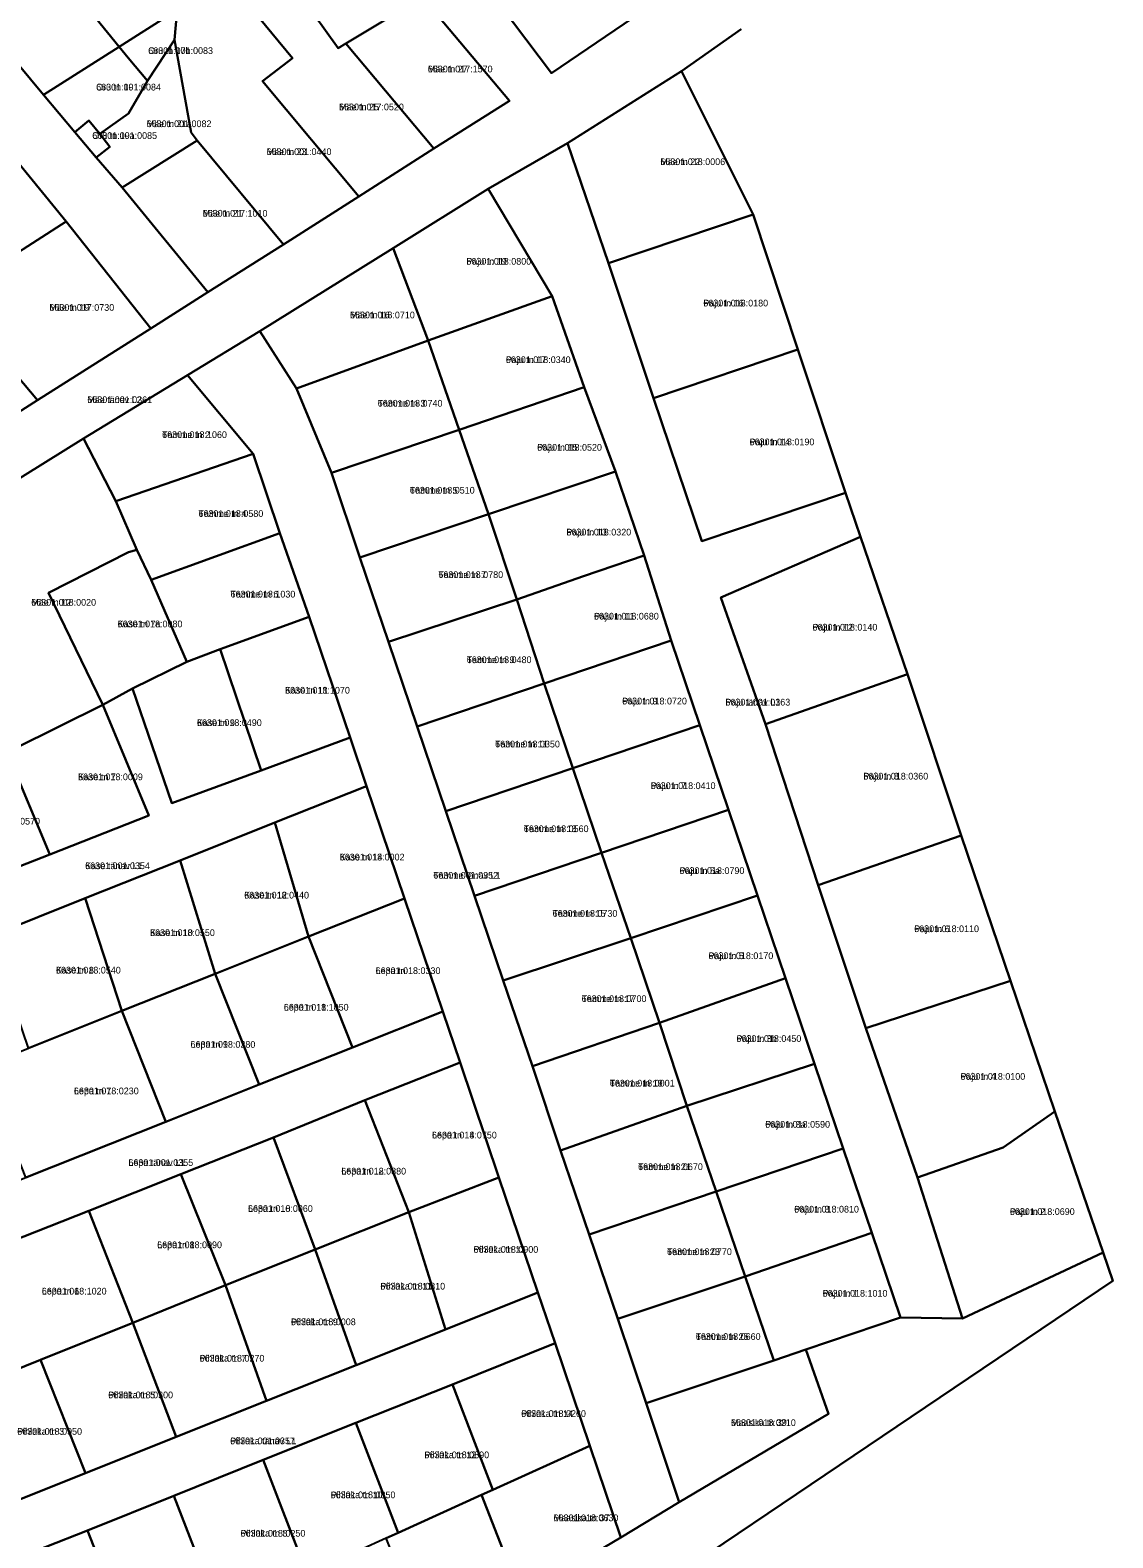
# Model space of a CAD drawing. Extents: x 632278 to 636344, y 6578401 to 6583362.
# Drawn here: x 634681.3 to 634923.7, y 6579573.7 to 6579911.1 of the extents above; entities that cross this region are included whole.
import ezdxf

# ---------------------------------------------------------------- set-up
doc = ezdxf.new("R2010")
doc.units = 0
for name, color, linetype in [('L_AADRESS', 7, 'Continuous'), ('PIIR', 7, 'Continuous'), ('TUNNUS', 7, 'Continuous')]:
    doc.layers.add(name, color=color, linetype=linetype)

msp = doc.modelspace()

# ---------------------------------------------------------------- linework, layer by layer
at = {"layer": 'PIIR'}
for points in [[(634732.89, 6580024.54), (634829.01, 6580019.04), (634843.75, 6579980.63), (634826.43, 6579969), (634849.45, 6579936.6), (634838.42, 6579929.05), (634798.01, 6579901.48), (634781.03, 6579924.08), (634761.47, 6579947.6), (634728.84, 6579986.89), (634732.38, 6580010.94)], [(634682.27, 6579930.7), (634698.8, 6579941.36), (634713.35, 6579923.81), (634714.62, 6579922.27), (634714.27, 6579915.65), (634712.52, 6579914.54), (634701.22, 6579907.36)], [(634769.15, 6579918.49), (634752.02, 6579908.13), (634750.26, 6579907.07), (634733.98, 6579929.82), (634752.56, 6579941.83), (634770.4, 6579919.25)], [(634682.27, 6579930.7), (634701.22, 6579907.36), (634684.34, 6579896.64), (634664.99, 6579919.9)], [(634740.03, 6579904.85), (634730.81, 6579916.04), (634729.25, 6579926.79), (634733.98, 6579929.82), (634750.26, 6579907.07), (634752.02, 6579908.13), (634771.69, 6579884.62), (634754.9, 6579873.86), (634733.36, 6579899.72)], [(634738.01, 6579863.17), (634718.71, 6579886.44), (634717.38, 6579888.19), (634713.63, 6579908.98), (634714.27, 6579915.65), (634714.62, 6579922.27), (634724.25, 6579924.06), (634730.81, 6579916.04), (634740.03, 6579904.85), (634733.36, 6579899.72), (634754.9, 6579873.86)], [(634769.15, 6579918.49), (634788.63, 6579895.28), (634771.69, 6579884.62), (634752.02, 6579908.13)], [(634703.24, 6579904.94), (634701.22, 6579907.36), (634712.52, 6579914.54), (634714.27, 6579915.65), (634713.63, 6579908.98), (634707.56, 6579899.77)], [(634701.89, 6579875.88), (634696.1, 6579882.61), (634699.14, 6579884.99), (634696.9, 6579887.89), (634703.32, 6579892.46), (634707.28, 6579899.29), (634707.56, 6579899.77), (634713.63, 6579908.98), (634717.38, 6579888.19), (634718.71, 6579886.44)], [(634691.32, 6579888.28), (634684.34, 6579896.64), (634701.22, 6579907.36), (634703.24, 6579904.94), (634707.56, 6579899.77), (634707.28, 6579899.29), (634703.32, 6579892.46), (634696.9, 6579887.89), (634694.43, 6579890.9)], [(634801.62, 6579885.85), (634827.14, 6579901.97), (634843.13, 6579869.84), (634810.8, 6579859)], [(634629.12, 6579865.11), (634670.45, 6579891.41), (634689.37, 6579868.32), (634663.35, 6579851.57), (634645.22, 6579840.07)], [(634696.1, 6579882.61), (634691.32, 6579888.28), (634694.43, 6579890.9), (634696.9, 6579887.89), (634699.14, 6579884.99)], [(634718.71, 6579886.44), (634738.01, 6579863.17), (634721.08, 6579852.45), (634701.89, 6579875.88)], [(634801.62, 6579885.85), (634810.8, 6579859), (634820.83, 6579828.73), (634831.68, 6579796.79), (634863.84, 6579807.62), (634867.14, 6579797.73), (634835.9, 6579784.18), (634845.93, 6579755.79), (634857.66, 6579719.81), (634868.39, 6579687.76), (634879.91, 6579654.41), (634890.03, 6579622.82), (634876.1, 6579623.06), (634869.69, 6579642.01), (634863.31, 6579660.86), (634856.89, 6579679.8), (634850.37, 6579698.99), (634844.15, 6579717.46), (634837.65, 6579736.63), (634831.23, 6579755.57), (634824.82, 6579774.51), (634818.74, 6579793.57), (634812.31, 6579812.38), (634805.35, 6579831.2), (634798.15, 6579851.57), (634783.84, 6579875.6)], [(634762.6, 6579862.34), (634783.84, 6579875.6), (634798.15, 6579851.57), (634770.4, 6579841.68)], [(634853.17, 6579839.67), (634820.83, 6579828.73), (634810.8, 6579859), (634843.13, 6579869.84)], [(634663.35, 6579851.57), (634689.37, 6579868.32), (634708.31, 6579844.36), (634682.99, 6579828.3)], [(634740.98, 6579830.94), (634732.72, 6579843.79), (634762.6, 6579862.34), (634770.4, 6579841.68)], [(634638.39, 6579835.72), (634645.22, 6579840.07), (634663.35, 6579851.57), (634682.99, 6579828.3), (634657.65, 6579812.24)], [(634777.38, 6579821.67), (634770.4, 6579841.68), (634798.15, 6579851.57), (634805.35, 6579831.2)], [(634732.72, 6579843.79), (634740.98, 6579830.94), (634748.74, 6579812.09), (634755.15, 6579793.15), (634761.57, 6579774.21), (634767.98, 6579755.26), (634774.4, 6579736.32), (634780.81, 6579717.38), (634787.23, 6579698.44), (634793.74, 6579679.32), (634800.03, 6579660.44), (634806.47, 6579641.61), (634812.84, 6579622.78), (634819.22, 6579603.86), (634826.58, 6579581.7), (634813.54, 6579573.83), (634806.6, 6579594.36), (634798.83, 6579617.27), (634794.98, 6579628.64), (634786.26, 6579654.39), (634777.55, 6579680.14), (634773.69, 6579691.51), (634765.12, 6579716.84), (634756.61, 6579741.95), (634752.95, 6579752.8), (634743.77, 6579779.85), (634737.19, 6579798.56), (634731.23, 6579816.28), (634716.55, 6579833.95)], [(634740.98, 6579830.94), (634770.4, 6579841.68), (634777.38, 6579821.67), (634748.74, 6579812.09)], [(634820.83, 6579828.73), (634853.17, 6579839.67), (634863.84, 6579807.62), (634831.68, 6579796.79)], [(634693.26, 6579819.72), (634716.55, 6579833.95), (634731.23, 6579816.28), (634700.53, 6579805.75)], [(634777.38, 6579821.67), (634805.35, 6579831.2), (634812.31, 6579812.38), (634783.91, 6579802.82)], [(634783.91, 6579802.82), (634755.15, 6579793.15), (634748.74, 6579812.09), (634777.38, 6579821.67)], [(634693.26, 6579819.72), (634694.29, 6579817.75), (634700.53, 6579805.75), (634705.2, 6579794.83), (634703.35, 6579794.3), (634685.42, 6579785.24), (634697.58, 6579760.13), (634677.89, 6579750.37), (634657.96, 6579797.78)], [(634705.2, 6579794.83), (634700.53, 6579805.75), (634731.23, 6579816.28), (634737.19, 6579798.56), (634708.4, 6579788.09)], [(634818.74, 6579793.57), (634805.14, 6579788.97), (634790.26, 6579783.7), (634783.91, 6579802.82), (634812.31, 6579812.38)], [(634755.15, 6579793.15), (634783.91, 6579802.82), (634790.26, 6579783.7), (634761.57, 6579774.21)], [(634716.39, 6579769.77), (634708.4, 6579788.09), (634737.19, 6579798.56), (634743.77, 6579779.85), (634723.83, 6579772.57)], [(634845.93, 6579755.79), (634835.9, 6579784.18), (634867.15, 6579797.74), (634877.71, 6579767.04)], [(634685.42, 6579785.24), (634703.35, 6579794.3), (634705.2, 6579794.83), (634708.4, 6579788.09), (634716.39, 6579769.77), (634704.27, 6579763.78), (634697.58, 6579760.13)], [(634790.26, 6579783.7), (634805.14, 6579788.97), (634818.74, 6579793.57), (634824.82, 6579774.51), (634796.4, 6579764.89)], [(634761.57, 6579774.21), (634790.26, 6579783.7), (634796.4, 6579764.89), (634767.98, 6579755.26)], [(634723.83, 6579772.57), (634743.77, 6579779.85), (634752.95, 6579752.8), (634733.04, 6579745.47)], [(634796.4, 6579764.89), (634824.82, 6579774.51), (634831.23, 6579755.57), (634802.81, 6579745.94)], [(634704.27, 6579763.78), (634716.39, 6579769.77), (634723.83, 6579772.57), (634733.04, 6579745.47), (634713.06, 6579738.12)], [(634774.4, 6579736.32), (634767.98, 6579755.26), (634796.4, 6579764.89), (634802.81, 6579745.94)], [(634845.93, 6579755.79), (634877.71, 6579767.04), (634889.72, 6579730.89), (634857.66, 6579719.81)], [(634604.33, 6579694.26), (634631.73, 6579705.13), (634636.19, 6579706.92), (634661.99, 6579717.4), (634685.7, 6579726.66), (634707.88, 6579735.39), (634697.58, 6579760.13), (634704.27, 6579763.78), (634713.06, 6579738.12), (634733.04, 6579745.47), (634752.95, 6579752.8), (634756.61, 6579741.95), (634736.13, 6579733.8), (634714.87, 6579725.33), (634693.61, 6579716.85), (634672.35, 6579708.38), (634651.17, 6579699.82), (634629.98, 6579691.23), (634608.56, 6579682.97)], [(634676.23, 6579749.31), (634677.89, 6579750.37), (634697.58, 6579760.13), (634707.88, 6579735.39), (634685.7, 6579726.66)], [(634831.23, 6579755.57), (634837.65, 6579736.63), (634809.23, 6579727), (634802.81, 6579745.94)], [(634653.12, 6579738.16), (634676.23, 6579749.31), (634685.7, 6579726.66), (634661.99, 6579717.4)], [(634774.4, 6579736.32), (634802.81, 6579745.94), (634809.23, 6579727), (634780.81, 6579717.38)], [(634756.61, 6579741.95), (634765.12, 6579716.84), (634743.61, 6579708.28), (634736.13, 6579733.8)], [(634714.87, 6579725.33), (634736.13, 6579733.8), (634743.61, 6579708.28), (634722.73, 6579699.96)], [(634809.23, 6579727), (634837.65, 6579736.63), (634844.15, 6579717.46), (634815.76, 6579707.94)], [(634857.66, 6579719.81), (634889.72, 6579730.89), (634900.72, 6579698.39), (634868.39, 6579687.76)], [(634780.81, 6579717.38), (634809.23, 6579727), (634815.76, 6579707.94), (634787.23, 6579698.44)], [(634693.61, 6579716.85), (634714.87, 6579725.33), (634722.73, 6579699.96), (634701.86, 6579691.65)], [(634672.35, 6579708.38), (634693.61, 6579716.85), (634701.86, 6579691.65), (634680.98, 6579683.34)], [(634753.48, 6579683.47), (634743.61, 6579708.28), (634765.12, 6579716.84), (634773.69, 6579691.51)], [(634850.37, 6579698.99), (634822.22, 6579689.01), (634815.76, 6579707.94), (634844.15, 6579717.46)], [(634722.73, 6579699.96), (634743.61, 6579708.28), (634753.48, 6579683.47), (634732.6, 6579675.16)], [(634787.23, 6579698.44), (634815.76, 6579707.94), (634822.22, 6579689.01), (634793.74, 6579679.32)], [(634701.86, 6579691.65), (634722.73, 6579699.96), (634732.6, 6579675.16), (634711.73, 6579666.85)], [(634822.22, 6579689.01), (634850.37, 6579698.99), (634856.89, 6579679.8), (634828.27, 6579670.44)], [(634910.69, 6579669.18), (634899.07, 6579661.08), (634879.91, 6579654.41), (634868.39, 6579687.76), (634900.72, 6579698.39)], [(634628.21, 6579633.58), (634649.09, 6579641.9), (634680.4, 6579654.36), (634711.73, 6579666.85), (634732.6, 6579675.16), (634753.48, 6579683.47), (634773.69, 6579691.51), (634777.55, 6579680.14), (634756.27, 6579671.66), (634735.83, 6579663.34), (634715.06, 6579655.14), (634694.46, 6579646.91), (634673.8, 6579638.81), (634663.48, 6579634.7), (634653.14, 6579630.6), (634632.65, 6579622.43)], [(634680.98, 6579683.34), (634701.86, 6579691.65), (634711.73, 6579666.85), (634680.4, 6579654.36), (634670.53, 6579679.17)], [(634822.22, 6579689.01), (634828.27, 6579670.44), (634800.03, 6579660.44), (634793.74, 6579679.32)], [(634756.27, 6579671.66), (634777.55, 6579680.14), (634786.26, 6579654.39), (634766.12, 6579646.6)], [(634828.27, 6579670.44), (634856.89, 6579679.8), (634863.31, 6579660.86), (634834.89, 6579651.24)], [(634735.83, 6579663.34), (634756.27, 6579671.66), (634766.12, 6579646.6), (634745.12, 6579638.24)], [(634800.03, 6579660.44), (634828.27, 6579670.44), (634834.89, 6579651.24), (634806.47, 6579641.61)], [(634879.91, 6579654.41), (634899.07, 6579661.08), (634910.69, 6579669.18), (634921.5, 6579637.56), (634890.03, 6579622.82)], [(634715.06, 6579655.14), (634735.83, 6579663.34), (634745.12, 6579638.24), (634725.06, 6579630.3)], [(634834.89, 6579651.24), (634863.31, 6579660.86), (634869.69, 6579642.01), (634841.34, 6579632.2)], [(634725.06, 6579630.3), (634704.31, 6579621.89), (634694.46, 6579646.91), (634715.06, 6579655.14)], [(634766.12, 6579646.6), (634786.26, 6579654.39), (634794.98, 6579628.64), (634774.3, 6579620.37)], [(634806.47, 6579641.61), (634834.89, 6579651.24), (634841.34, 6579632.2), (634812.84, 6579622.78)], [(634663.48, 6579634.7), (634673.8, 6579638.81), (634694.46, 6579646.91), (634704.31, 6579621.89), (634683.63, 6579613.55), (634673.4, 6579609.46)], [(634754.33, 6579612.41), (634745.12, 6579638.24), (634766.12, 6579646.6), (634774.3, 6579620.37)], [(634847.76, 6579613.41), (634841.34, 6579632.2), (634869.69, 6579642.01), (634876.1, 6579623.06), (634854.96, 6579615.86)], [(634592.69, 6579461.83), (634631, 6579479.99), (634648.01, 6579488.06), (634654.56, 6579491.17), (634660.15, 6579493.54), (634666.58, 6579496.26), (634680.46, 6579502.21), (634698.33, 6579510.56), (634716.42, 6579519.01), (634734.7, 6579527.54), (634753.41, 6579536.32), (634771.02, 6579548.58), (634791.22, 6579560.58), (634813.54, 6579573.83), (634826.58, 6579581.7), (634860.03, 6579601.48), (634854.96, 6579615.86), (634876.1, 6579623.06), (634890.03, 6579622.82), (634921.5, 6579637.56), (634923.65, 6579631.25), (634762.59, 6579522.66), (634626.39, 6579457.25), (634598.82, 6579446.11)], [(634725.06, 6579630.3), (634745.12, 6579638.24), (634754.33, 6579612.41), (634734.2, 6579604.38)], [(634704.31, 6579621.89), (634725.06, 6579630.3), (634734.2, 6579604.38), (634713.99, 6579596.32)], [(634812.84, 6579622.78), (634841.34, 6579632.2), (634847.76, 6579613.41), (634819.22, 6579603.86)], [(634652.76, 6579571.88), (634673.25, 6579580.06), (634693.7, 6579588.22), (634713.99, 6579596.32), (634734.2, 6579604.38), (634754.33, 6579612.41), (634774.3, 6579620.37), (634794.98, 6579628.64), (634798.83, 6579617.27), (634775.84, 6579608.09), (634754.24, 6579599.46), (634733.47, 6579591.17), (634713.52, 6579583.12), (634694.18, 6579575.4), (634675.19, 6579567.91), (634657.19, 6579560.73)], [(634683.63, 6579613.55), (634704.31, 6579621.89), (634713.99, 6579596.32), (634693.7, 6579588.22)], [(634784.88, 6579584.5), (634775.84, 6579608.09), (634798.83, 6579617.27), (634806.6, 6579594.36)], [(634826.58, 6579581.7), (634819.22, 6579603.86), (634847.76, 6579613.41), (634854.96, 6579615.86), (634860.03, 6579601.48)], [(634663.18, 6579605.36), (634673.4, 6579609.46), (634683.63, 6579613.55), (634693.7, 6579588.22), (634673.25, 6579580.06)], [(634754.24, 6579599.46), (634775.84, 6579608.09), (634784.88, 6579584.5), (634782.37, 6579583.36), (634763.7, 6579574.88)], [(634733.47, 6579591.17), (634754.24, 6579599.46), (634763.7, 6579574.88), (634760.98, 6579573.65), (634743.34, 6579565.64)], [(634782.37, 6579583.36), (634784.88, 6579584.5), (634806.6, 6579594.36), (634813.54, 6579573.83), (634791.22, 6579560.58)], [(634713.52, 6579583.12), (634733.47, 6579591.17), (634743.34, 6579565.64), (634741.45, 6579564.78), (634723.68, 6579556.73)], [(634694.18, 6579575.4), (634713.52, 6579583.12), (634723.68, 6579556.73), (634723.02, 6579556.37), (634704.86, 6579548.14)], [(634760.98, 6579573.65), (634763.7, 6579574.88), (634782.37, 6579583.36), (634791.22, 6579560.58), (634771.02, 6579548.58)], [(634675.19, 6579567.91), (634694.18, 6579575.4), (634704.86, 6579548.14), (634686.78, 6579540.03)]]:
    msp.add_lwpolyline(points, close=True, dxfattribs=at)
for points in [[(634781.03, 6579924.08), (634798.01, 6579901.48), (634838.42, 6579929.05)], [(634664.99, 6579919.9), (634684.34, 6579896.64), (634691.32, 6579888.28), (634696.1, 6579882.61), (634701.89, 6579875.88), (634721.08, 6579852.45), (634708.31, 6579844.36), (634689.37, 6579868.32), (634670.45, 6579891.41), (634665.82, 6579901.86), (634648.9, 6579922.66)], [(634657.65, 6579812.24), (634682.99, 6579828.3), (634708.31, 6579844.36), (634721.08, 6579852.45), (634738.01, 6579863.17), (634754.9, 6579873.86), (634771.69, 6579884.62), (634788.63, 6579895.28), (634769.15, 6579918.49)], [(634683.61, 6578861.97), (634681.47, 6578962.07), (634668.96, 6578959.68), (634659.72, 6579055.77), (634657.39, 6579079.77), (634640.69, 6579253.02), (634619.84, 6579395.9), (634646.99, 6579406.93), (634634.13, 6579438.99), (634626.39, 6579457.25), (634762.59, 6579522.66), (634923.65, 6579631.25), (634921.5, 6579637.56), (634910.69, 6579669.18), (634900.72, 6579698.39), (634889.72, 6579730.89), (634877.71, 6579767.04), (634867.15, 6579797.74), (634863.84, 6579807.62), (634853.17, 6579839.67), (634843.13, 6579869.84), (634827.14, 6579901.97), (634840.49, 6579911.35)], [(634840.49, 6579911.35), (634827.14, 6579901.97), (634801.62, 6579885.85), (634783.84, 6579875.6), (634762.6, 6579862.34), (634732.72, 6579843.79), (634716.55, 6579833.95), (634693.26, 6579819.72), (634657.96, 6579797.78)]]:
    msp.add_lwpolyline(points, dxfattribs=at)

# ---------------------------------------------------------------- texts
at = {"layer": 'L_AADRESS'}
for s, p in [('Oru tn 17b', (634707.75, 6579905.78)), ('Mäe tn 27', (634770.33, 6579901.67)), ('Oru tn 19', (634696.1, 6579897.62)), ('Mäe tn 25', (634750.47, 6579893.19)), ('Mäe tn 21a', (634707.41, 6579889.42)), ('Oru tn 19a', (634695.23, 6579886.78)), ('Mäe tn 23', (634734.27, 6579883.16)), ('Mäe tn 22', (634822.38, 6579880.92)), ('Mäe tn 21', (634719.95, 6579869.39)), ('Paju tn 19', (634778.97, 6579858.64)), ('Mäe tn 19', (634685.64, 6579848.31)), ('Paju tn 16', (634831.99, 6579849.29)), ('Mäe tn 16', (634752.92, 6579846.64)), ('Paju tn 17', (634787.8, 6579836.62)), ('Mäe tänav L2', (634694.13, 6579827.67)), ('Tamme tn 3', (634759.11, 6579826.88)), ('Tamme tn 2', (634710.87, 6579819.85)), ('Paju tn 15', (634794.8, 6579817.01)), ('Paju tn 14', (634842.35, 6579818.23)), ('Tamme tn 5', (634766.32, 6579807.41)), ('Tamme tn 4', (634719.01, 6579802.19)), ('Paju tn 13', (634801.35, 6579798.04)), ('Tamme tn 7', (634772.69, 6579788.52)), ('Tamme tn 6', (634726.18, 6579784.16)), ('Mäe tn 12', (634681.58, 6579782.33)), ('Paju tn 11', (634807.52, 6579779.23)), ('Kase tn 7a', (634700.91, 6579777.5)), ('Paju tn 12', (634856.44, 6579776.76)), ('Tamme tn 9', (634779.04, 6579769.48)), ('Kase tn 11', (634738.39, 6579762.66)), ('Paju tn 9', (634813.82, 6579760.23)), ('Paju tänav L1', (634836.94, 6579759.99)), ('Kase tn 9', (634718.66, 6579755.4)), ('Tamme tn 11', (634785.39, 6579750.61)), ('Kase tn 7', (634692.05, 6579743.28)), ('Paju tn 8', (634867.82, 6579743.43)), ('Paju tn 7', (634820.23, 6579741.29)), ('Tamme tn 13', (634791.81, 6579731.66)), ('Kase tn 14', (634750.62, 6579725.32)), ('Kase tänav L1', (634693.63, 6579723.38)), ('Paju tn 5a', (634826.68, 6579722.29)), ('Tamme tänav L1', (634771.56, 6579721.24)), ('Kase tn 12', (634729.24, 6579716.8)), ('Tamme tn 15', (634798.26, 6579712.72)), ('Kase tn 10', (634708.17, 6579708.41)), ('Paju tn 6', (634879.19, 6579709.28)), ('Paju tn 5', (634833.15, 6579703.24)), ('Kase tn 8', (634687.11, 6579700.02)), ('Lepa tn 13', (634758.65, 6579699.9)), ('Lepa tn 11', (634738.1, 6579691.72)), ('Tamme tn 17', (634804.76, 6579693.63)), ('Lepa tn 9', (634717.23, 6579683.41)), ('Paju tn 3b', (634839.42, 6579684.71)), ('Tamme tn 19', (634811.07, 6579674.73)), ('Paju tn 4', (634889.54, 6579676.24)), ('Lepa tn 7', (634691.13, 6579673)), ('Paju tn 3a', (634845.85, 6579665.52)), ('Lepa tn 14', (634771.27, 6579663.11)), ('Lepa tänav L1', (634703.32, 6579656.97)), ('Lepa tn 12', (634750.97, 6579655.04)), ('Tamme tn 21', (634817.39, 6579656.03)), ('Lepa tn 10', (634730.09, 6579646.68)), ('Paju tn 3', (634852.32, 6579646.53)), ('Paju tn 2', (634900.61, 6579646)), ('Lepa tn 8', (634709.76, 6579638.56)), ('Pihlaka tn 13', (634780.55, 6579637.53)), ('Tamme tn 23', (634823.87, 6579637.01)), ('Lepa tn 6', (634683.94, 6579628.19)), ('Pihlaka tn 11', (634759.71, 6579629.3)), ('Paju tn 1', (634858.7, 6579627.71)), ('Pihlaka tn 9', (634739.7, 6579621.33)), ('Tamme tn 25', (634830.31, 6579618.03)), ('Pihlaka tn 7', (634719.26, 6579613.18)), ('Pihlaka tn 5', (634698.81, 6579604.97)), ('Pihlaka tn 14', (634791.22, 6579600.8)), ('Maasika tn 39', (634838.19, 6579598.78)), ('Pihlaka tn 3', (634678.44, 6579596.8)), ('Pihlaka tänav L1', (634726.09, 6579594.69)), ('Pihlaka tn 12', (634769.56, 6579591.56)), ('Pihlaka tn 10', (634748.59, 6579582.61)), ('Maasika tn 37', (634798.48, 6579577.47)), ('Pihlaka tn 8', (634728.43, 6579574.01))]:
    msp.add_text(s, height=1.5, dxfattribs=at).set_placement(p)
at = {"layer": 'TUNNUS'}
for s, p in [('66301:001:0083', (634707.75, 6579905.78)), ('66301:017:1570', (634770.33, 6579901.67)), ('66301:001:0084', (634696.1, 6579897.62)), ('66301:017:0520', (634750.47, 6579893.19)), ('66301:001:0082', (634707.41, 6579889.42)), ('66301:001:0085', (634695.23, 6579886.78)), ('66301:001:0440', (634734.27, 6579883.16)), ('66301:018:0006', (634822.38, 6579880.92)), ('66301:017:1010', (634719.95, 6579869.39)), ('66301:018:0800', (634778.97, 6579858.64)), ('66301:017:0730', (634685.64, 6579848.31)), ('66301:018:0180', (634831.99, 6579849.29)), ('66301:018:0710', (634752.92, 6579846.64)), ('66301:018:0340', (634787.8, 6579836.62)), ('66301:001:0361', (634694.13, 6579827.67)), ('66301:018:0740', (634759.11, 6579826.88)), ('66301:018:1060', (634710.87, 6579819.85)), ('66301:018:0520', (634794.8, 6579817.01)), ('66301:018:0190', (634842.35, 6579818.23)), ('66301:018:0510', (634766.32, 6579807.41)), ('66301:018:0580', (634719.01, 6579802.19)), ('66301:018:0320', (634801.35, 6579798.04)), ('66301:018:0780', (634772.69, 6579788.52)), ('66301:018:1030', (634726.18, 6579784.16)), ('66301:018:0020', (634681.58, 6579782.33)), ('66301:018:0080', (634700.91, 6579777.5)), ('66301:018:0680', (634807.52, 6579779.23)), ('66301:018:0140', (634856.44, 6579776.76)), ('66301:018:0480', (634779.04, 6579769.48)), ('66301:018:1070', (634738.39, 6579762.66)), ('66301:018:0720', (634813.82, 6579760.23)), ('66301:001:0363', (634836.94, 6579759.99)), ('66301:018:0490', (634718.66, 6579755.4)), ('66301:018:0350', (634785.39, 6579750.61)), ('66301:018:0009', (634692.05, 6579743.28)), ('66301:018:0360', (634867.82, 6579743.43)), ('66301:018:0410', (634820.23, 6579741.29)), ('66301:018:0570', (634669.04, 6579733.35)), ('66301:018:0560', (634791.81, 6579731.66)), ('66301:018:0002', (634750.62, 6579725.32)), ('66301:001:0354', (634693.63, 6579723.38)), ('66301:018:0790', (634826.68, 6579722.29)), ('66301:001:0352', (634771.56, 6579721.24)), ('66301:018:0440', (634729.24, 6579716.8)), ('66301:018:0730', (634798.26, 6579712.72)), ('66301:018:0550', (634708.17, 6579708.41)), ('66301:018:0110', (634879.19, 6579709.28)), ('66301:018:0170', (634833.15, 6579703.24)), ('66301:018:0540', (634687.11, 6579700.02)), ('66301:018:0330', (634758.65, 6579699.9)), ('66301:018:1050', (634738.1, 6579691.72)), ('66301:018:0700', (634804.76, 6579693.63)), ('66301:018:0280', (634717.23, 6579683.41)), ('66301:018:0450', (634839.42, 6579684.71)), ('66301:018:0001', (634811.07, 6579674.73)), ('66301:018:0100', (634889.54, 6579676.24)), ('66301:018:0230', (634691.13, 6579673)), ('66301:018:0590', (634845.85, 6579665.52)), ('66301:018:0750', (634771.27, 6579663.11)), ('66301:001:0355', (634703.32, 6579656.97)), ('66301:018:0880', (634750.97, 6579655.04)), ('66301:018:0670', (634817.39, 6579656.03)), ('66301:018:0060', (634730.09, 6579646.68)), ('66301:018:0810', (634852.32, 6579646.53)), ('66301:018:0690', (634900.61, 6579646)), ('66301:018:0090', (634709.76, 6579638.56)), ('66301:018:0900', (634780.55, 6579637.53)), ('66301:018:0770', (634823.87, 6579637.01)), ('66301:018:1020', (634683.94, 6579628.19)), ('66301:018:0310', (634759.71, 6579629.3)), ('66301:018:1010', (634858.7, 6579627.71)), ('66301:018:0008', (634739.7, 6579621.33)), ('66301:018:0660', (634830.31, 6579618.03)), ('66301:018:0270', (634719.26, 6579613.18)), ('66301:018:0300', (634698.81, 6579604.97)), ('66301:018:0260', (634791.22, 6579600.8)), ('66301:018:0210', (634838.19, 6579598.78)), ('66301:018:0950', (634678.44, 6579596.8)), ('66301:001:0357', (634726.09, 6579594.69)), ('66301:018:0890', (634769.56, 6579591.56)), ('66301:018:0850', (634748.59, 6579582.61)), ('66301:018:0630', (634798.48, 6579577.47)), ('66301:018:0250', (634728.43, 6579574.01))]:
    msp.add_text(s, height=1.5, dxfattribs=at).set_placement(p)

doc.saveas('drawing.dxf')
